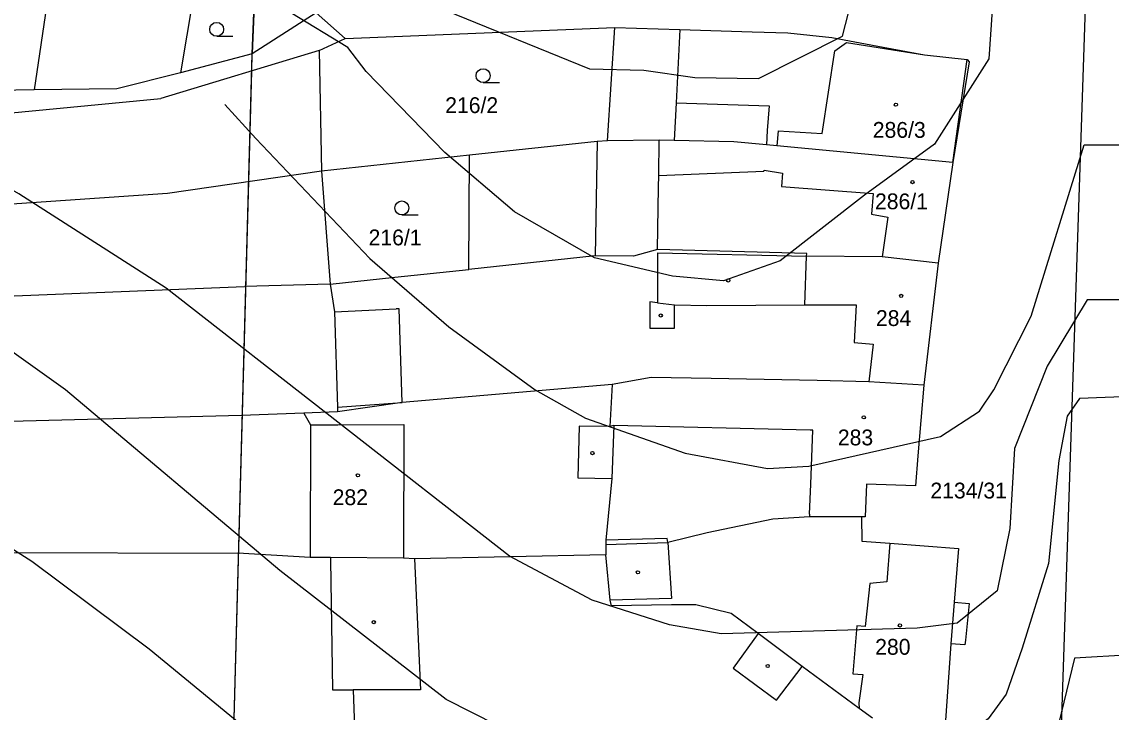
# Model space of a CAD drawing. Extents: x -555860 to -552701, y -1187050 to -1182291.
# Drawn here: x -554722.7 to -554605.7, y -1184771.9 to -1184697.7 of the extents above; entities that cross this region are included whole.
import ezdxf

# ---------------------------------------------------------------- set-up
doc = ezdxf.new("R2010")
doc.units = 0
for name, color, linetype in [('CYKLISTI_stav', 7, 'Continuous'), ('LEG_2b', 7, 'Continuous'), ('Level 25', 7, 'Continuous'), ('Level 32', 7, 'Continuous'), ('Level 40', 7, 'Continuous'), ('Level 41', 7, 'Continuous'), ('navrh_BV', 7, 'Continuous'), ('Poz předměty', 7, 'Continuous')]:
    doc.layers.add(name, color=color, linetype=linetype)

msp = doc.modelspace()

# ---------------------------------------------------------------- linework, layer by layer
at = {"layer": 'CYKLISTI_stav'}
for p, q in [((-554652.03, -1184698.53), (-554652.43, -1184706.42)), ((-554622.69, -1184712.83), (-554621.15, -1184701.75)), ((-554652.43, -1184706.42), (-554652.64, -1184710.45)), ((-554642.63, -1184709.37), (-554642.73, -1184710.92)), ((-554641.48, -1184709.43), (-554641.59, -1184711.03)), ((-554660.89, -1184710.57), (-554661.13, -1184722.87)), ((-554654.29, -1184714.23), (-554654.23, -1184710.41)), ((-554654.31, -1184715.48), (-554654.29, -1184714.23)), ((-554654.29, -1184714.23), (-554643, -1184713.77)), ((-554643, -1184713.77), (-554642.98, -1184713.66)), ((-554642.98, -1184713.66), (-554641, -1184713.97)), ((-554641, -1184713.97), (-554641.11, -1184715.42)), ((-554654.41, -1184722.17), (-554654.31, -1184715.48)), ((-554641.11, -1184715.42), (-554631.26, -1184716.14)), ((-554631.26, -1184716.14), (-554631.42, -1184718.37)), ((-554631.42, -1184718.37), (-554629.68, -1184718.69)), ((-554629.68, -1184718.69), (-554630.28, -1184722.98)), ((-554654.41, -1184722.52), (-554654.43, -1184727.9)), ((-554654.41, -1184722.52), (-554638.43, -1184722.91)), ((-554638.58, -1184728.14), (-554638.43, -1184722.91)), ((-554655.24, -1184727.8), (-554655.25, -1184730.62)), ((-554654.43, -1184727.9), (-554655.24, -1184727.8)), ((-554654.43, -1184727.9), (-554652.6, -1184728.14)), ((-554652.61, -1184730.64), (-554652.6, -1184728.14)), ((-554652.6, -1184728.14), (-554649.13, -1184728.19)), ((-554649.13, -1184728.19), (-554638.58, -1184728.14)), ((-554638.58, -1184728.14), (-554633.27, -1184728.11)), ((-554633.08, -1184728.11), (-554633.29, -1184732.17)), ((-554633.27, -1184728.11), (-554633.08, -1184728.11)), ((-554689.11, -1184728.89), (-554682.49, -1184728.57)), ((-554682.16, -1184728.55), (-554682.49, -1184728.57)), ((-554681.84, -1184738.64), (-554682.16, -1184728.55)), ((-554655.25, -1184730.62), (-554652.61, -1184730.64)), ((-554633.29, -1184732.17), (-554631.26, -1184732.37)), ((-554631.26, -1184732.37), (-554631.71, -1184736.39)), ((-554688.81, -1184739.12), (-554681.84, -1184738.64)), ((-554691.71, -1184741.03), (-554688.76, -1184741.02)), ((-554688.76, -1184741.02), (-554681.67, -1184741)), ((-554681.67, -1184741), (-554681.72, -1184755.36)), ((-554659.13, -1184741.1), (-554659.56, -1184741.22)), ((-554659.13, -1184741.1), (-554659.33, -1184746.81)), ((-554638.02, -1184741.6), (-554659.13, -1184741.1)), ((-554637.75, -1184741.61), (-554638.02, -1184741.6)), ((-554637.95, -1184747.41), (-554637.75, -1184741.61)), ((-554638.08, -1184750.62), (-554637.95, -1184747.41)), ((-554638.08, -1184750.62), (-554638.08, -1184750.92)), ((-554659.98, -1184753.88), (-554653.3, -1184753.68)), ((-554653.3, -1184753.68), (-554652.93, -1184759.71)), ((-554629.48, -1184753.75), (-554629.79, -1184757.9)), ((-554680.54, -1184755.42), (-554679.88, -1184769.53)), ((-554631.61, -1184758.09), (-554632.1, -1184762.72)), ((-554629.79, -1184757.9), (-554631.61, -1184758.09)), ((-554652.93, -1184759.71), (-554659.5, -1184759.89)), ((-554622.57, -1184760.1), (-554622.9, -1184764.57)), ((-554643.61, -1184763.47), (-554646.3, -1184767.17)), ((-554633.01, -1184762.64), (-554633.45, -1184767.78)), ((-554632.1, -1184762.72), (-554633.01, -1184762.64)), ((-554641.65, -1184770.63), (-554638.89, -1184767.02)), ((-554646.3, -1184767.17), (-554641.65, -1184770.63)), ((-554633.45, -1184767.78), (-554632.36, -1184767.87)), ((-554632.36, -1184767.87), (-554632.78, -1184770.91)), ((-554679.88, -1184769.53), (-554687.1, -1184769.51)), ((-554632.78, -1184770.91), (-554632.76, -1184771.51))]:
    msp.add_line(p, q, dxfattribs=at)
for points in [[(-554641.48, -1184709.43), (-554636.73, -1184709.69), (-554635.39, -1184700.81), (-554634.13, -1184699.94), (-554625.75, -1184701.24)], [(-554652.43, -1184706.42), (-554642.44, -1184706.74), (-554642.63, -1184709.37)]]:
    msp.add_lwpolyline(points, dxfattribs=at)
at = {"layer": 'Level 25'}
for p, q in [((-554701.78, -1184699.26), (-554700.03, -1184699.26)), ((-554673.16, -1184704.24), (-554671.41, -1184704.24)), ((-554681.89, -1184718.46), (-554680.14, -1184718.46))]:
    msp.add_line(p, q, dxfattribs=at)
for centre, radius in [((-554701.78, -1184698.51), 0.75), ((-554673.16, -1184703.49), 0.75), ((-554628.81, -1184706.61), 0.175), ((-554627.03, -1184714.93), 0.175), ((-554681.89, -1184717.71), 0.75), ((-554646.83, -1184725.5), 0.175), ((-554628.25, -1184727.17), 0.175), ((-554654.08, -1184729.27), 0.175), ((-554632.27, -1184740.22), 0.175), ((-554661.41, -1184744.06), 0.175), ((-554686.61, -1184746.45), 0.175), ((-554656.53, -1184756.88), 0.175), ((-554684.91, -1184762.24), 0.175), ((-554628.38, -1184762.59), 0.175), ((-554642.59, -1184766.95), 0.175)]:
    msp.add_circle(centre, radius, dxfattribs=at)
at = {"layer": 'Level 32'}
msp.add_lwpolyline([(-554717.6, -1184874.5), (-554713.44, -1184852.4), (-554706.92, -1184853.88), (-554706.04, -1184849.97), (-554712.7, -1184848.47), (-554700.16, -1184781.85), (-554697.96, -1184701.13), (-554696.6, -1184667.81), (-554694.47, -1184658.87), (-554690.37, -1184660.23)], dxfattribs=at)
at = {"layer": 'Level 40'}
msp.add_lwpolyline([(-554700.89, -1184706.6), (-554697.58, -1184710.26), (-554685.31, -1184723.13), (-554676.85, -1184730.48), (-554667.56, -1184737.28), (-554662.15, -1184740.32), (-554651.47, -1184744.07), (-554642.6, -1184745.73), (-554638.16, -1184745.46), (-554624.02, -1184742.27), (-554619.82, -1184739.54), (-554618.31, -1184737.26), (-554614.29, -1184729.35), (-554608.6, -1184710.94), (-554601.62, -1184710.94)], dxfattribs=at)
at = {"layer": 'Level 41'}
for points in [[(-554821.34, -1184643.77), (-554818.42, -1184648.81), (-554813.29, -1184656.72), (-554806.63, -1184663.23), (-554803.41, -1184664.98), (-554800.67, -1184666.14), (-554796.79, -1184667.11), (-554790.96, -1184667.53), (-554769.06, -1184667.11), (-554721.64, -1184669.89), (-554709.99, -1184671.97), (-554702.22, -1184675.85), (-554677.79, -1184690.8), (-554677.25, -1184696.44), (-554661.73, -1184702.75), (-554655.91, -1184702.89), (-554650.41, -1184703.69), (-554643.56, -1184703.8), (-554634.55, -1184699.23), (-554633.23, -1184694.03), (-554627.76, -1184688.75), (-554618.33, -1184676.13), (-554610.15, -1184660.6), (-554604.33, -1184651.58)], [(-554604.84, -1184668.25), (-554608.91, -1184676.41), (-554618.47, -1184696.44), (-554618.83, -1184701.69), (-554624.66, -1184710.84), (-554632.2, -1184716.34), (-554641.25, -1184723.39), (-554647.35, -1184725.53), (-554652.8, -1184725.04), (-554661.21, -1184723.06), (-554669.78, -1184718.14), (-554677.26, -1184711.76), (-554685.72, -1184703.03), (-554687.7, -1184700.46), (-554693.8, -1184696.72)], [(-554601.83, -1184727.59), (-554608.27, -1184727.59), (-554612.57, -1184734.71), (-554616.06, -1184743.57), (-554616.59, -1184752.16), (-554617.94, -1184758.87), (-554622.23, -1184762.36), (-554626.52, -1184762.9), (-554647.59, -1184763.48), (-554653.14, -1184762.51), (-554661.46, -1184759.88), (-554670.33, -1184755.16), (-554707.21, -1184726.32), (-554723.02, -1184716.2), (-554733.7, -1184710.1)], [(-554602.64, -1184737.93), (-554609.08, -1184738.2), (-554610.42, -1184740.08), (-554611.3, -1184744.85), (-554612.41, -1184755.94), (-554615.25, -1184765.05), (-554616.96, -1184769.99), (-554618.9, -1184772.63), (-554625.96, -1184778.04), (-554643.43, -1184781.09), (-554653.42, -1184780.54), (-554663.4, -1184777.49), (-554677.12, -1184770.55), (-554695.01, -1184756.69), (-554718.03, -1184737.28), (-554735.5, -1184724.8), (-554750.75, -1184716.48), (-554760.32, -1184712.77)], [(-554603.49, -1184765.74), (-554609.62, -1184766.12), (-554613.91, -1184783.84), (-554618.17, -1184790.02), (-554624.02, -1184794.82), (-554632.34, -1184796.9), (-554640.66, -1184797.73), (-554651.75, -1184797.18), (-554655.74, -1184796.74), (-554666.13, -1184794.26), (-554677.19, -1184789.48), (-554681.98, -1184786.64), (-554689.47, -1184781.23), (-554709.02, -1184765.15), (-554721.63, -1184755.72), (-554738, -1184745.32), (-554749.92, -1184738.94), (-554772.11, -1184728.96), (-554787.08, -1184723.55), (-554796.81, -1184720.58), (-554804.55, -1184718.83), (-554812.49, -1184718)]]:
    msp.add_lwpolyline(points, dxfattribs=at)
at = {"layer": 'navrh_BV'}
for p, q in [((-554694.25, -1184634.07), (-554705.66, -1184703.17)), ((-554713.39, -1184651.22), (-554721.4, -1184705.02)), ((-554696.6, -1184667.81), (-554697.96, -1184701.13)), ((-554612.53, -1184818.21), (-554608.32, -1184692.11)), ((-554691.11, -1184696.73), (-554697.96, -1184701.13)), ((-554691.11, -1184696.73), (-554687.98, -1184699.51)), ((-554687.98, -1184699.51), (-554659.02, -1184698.31)), ((-554659.78, -1184710.51), (-554659.02, -1184698.31)), ((-554659.02, -1184698.31), (-554652.03, -1184698.53)), ((-554652.03, -1184698.53), (-554644.24, -1184698.78)), ((-554644.24, -1184698.78), (-554640.42, -1184698.88)), ((-554640.42, -1184698.88), (-554635.71, -1184699.4)), ((-554690.76, -1184700.79), (-554687.98, -1184699.51)), ((-554635.71, -1184699.4), (-554630.19, -1184700.42)), ((-554690.76, -1184700.79), (-554707.77, -1184705.96)), ((-554697.96, -1184701.13), (-554705.66, -1184703.17)), ((-554690.76, -1184700.79), (-554690.53, -1184713.76)), ((-554630.19, -1184700.42), (-554625.75, -1184701.24)), ((-554625.75, -1184701.24), (-554621.15, -1184701.75)), ((-554620.96, -1184702.01), (-554622.69, -1184712.83)), ((-554621.15, -1184701.75), (-554620.96, -1184702.01)), ((-554705.66, -1184703.17), (-554712.5, -1184704.91)), ((-554721.4, -1184705.02), (-554736.82, -1184705.2)), ((-554712.5, -1184704.91), (-554721.4, -1184705.02)), ((-554759.48, -1184710.88), (-554707.77, -1184705.96)), ((-554660.89, -1184710.57), (-554674.62, -1184712.05)), ((-554659.78, -1184710.51), (-554660.89, -1184710.57)), ((-554654.23, -1184710.41), (-554659.78, -1184710.51)), ((-554652.64, -1184710.45), (-554654.23, -1184710.41)), ((-554646.24, -1184710.59), (-554652.64, -1184710.45)), ((-554642.73, -1184710.92), (-554646.24, -1184710.59)), ((-554674.62, -1184712.05), (-554690.53, -1184713.76)), ((-554674.68, -1184724.31), (-554674.62, -1184712.05)), ((-554641.59, -1184711.03), (-554642.73, -1184710.92)), ((-554622.69, -1184712.83), (-554641.59, -1184711.03)), ((-554622.69, -1184712.83), (-554624.28, -1184723.63)), ((-554690.53, -1184713.76), (-554707.05, -1184716.16)), ((-554690.53, -1184713.76), (-554689.6, -1184725.9)), ((-554707.05, -1184716.16), (-554759.01, -1184719.71)), ((-554654.41, -1184722.17), (-554657.02, -1184722.91)), ((-554638.38, -1184722.61), (-554654.41, -1184722.17)), ((-554661.13, -1184722.87), (-554674.68, -1184724.31)), ((-554657.02, -1184722.91), (-554661.13, -1184722.87)), ((-554638.43, -1184722.91), (-554638.38, -1184722.61)), ((-554630.28, -1184722.98), (-554638.43, -1184722.91)), ((-554624.28, -1184723.63), (-554630.28, -1184722.98)), ((-554624.28, -1184723.63), (-554625.81, -1184736.76)), ((-554682.64, -1184725.16), (-554674.68, -1184724.31)), ((-554689.6, -1184725.9), (-554698.8, -1184726.14)), ((-554689.6, -1184725.9), (-554682.64, -1184725.16)), ((-554689.6, -1184725.9), (-554689.11, -1184728.89)), ((-554758.36, -1184728.58), (-554698.8, -1184726.14)), ((-554689.11, -1184728.89), (-554688.81, -1184739.12)), ((-554655.11, -1184735.95), (-554659.29, -1184736.68)), ((-554648.65, -1184736.06), (-554655.11, -1184735.95)), ((-554637.28, -1184736.26), (-554648.65, -1184736.06)), ((-554631.71, -1184736.39), (-554637.28, -1184736.26)), ((-554625.81, -1184736.76), (-554631.71, -1184736.39)), ((-554659.29, -1184736.68), (-554681.84, -1184738.64)), ((-554659.29, -1184736.68), (-554659.56, -1184741.22)), ((-554625.81, -1184736.76), (-554626.45, -1184744.36)), ((-554681.84, -1184738.64), (-554688.8, -1184739.62)), ((-554699.1, -1184740.03), (-554776.18, -1184741.97)), ((-554692.41, -1184739.76), (-554699.1, -1184740.03)), ((-554688.8, -1184739.62), (-554692.41, -1184739.76)), ((-554692.41, -1184739.76), (-554691.71, -1184741.03)), ((-554688.81, -1184739.12), (-554688.8, -1184739.62)), ((-554691.71, -1184741.03), (-554691.75, -1184755.29)), ((-554662.84, -1184741.17), (-554663, -1184746.71)), ((-554659.56, -1184741.22), (-554662.84, -1184741.17)), ((-554626.45, -1184744.36), (-554626.72, -1184747.58)), ((-554663, -1184746.71), (-554659.33, -1184746.81)), ((-554659.33, -1184746.81), (-554659.97, -1184753.43)), ((-554631.99, -1184747.41), (-554632.1, -1184750.9)), ((-554626.72, -1184747.58), (-554631.99, -1184747.41)), ((-554642.02, -1184751.16), (-554649.1, -1184752.64)), ((-554638.08, -1184750.92), (-554642.02, -1184751.16)), ((-554632.5, -1184750.9), (-554638.08, -1184750.92)), ((-554632.1, -1184750.9), (-554632.5, -1184750.9)), ((-554632.5, -1184750.9), (-554632.47, -1184753.53)), ((-554649.1, -1184752.64), (-554653.3, -1184753.68)), ((-554659.98, -1184753.88), (-554659.99, -1184755)), ((-554659.97, -1184753.43), (-554659.98, -1184753.88)), ((-554653.37, -1184753.24), (-554659.97, -1184753.43)), ((-554653.3, -1184753.68), (-554653.37, -1184753.24)), ((-554632.47, -1184753.53), (-554629.48, -1184753.75)), ((-554629.48, -1184753.75), (-554622.1, -1184754.31)), ((-554775.16, -1184754.66), (-554699.5, -1184754.82)), ((-554691.75, -1184755.29), (-554699.5, -1184754.82)), ((-554689.55, -1184755.3), (-554691.75, -1184755.29)), ((-554681.72, -1184755.36), (-554689.55, -1184755.3)), ((-554689.55, -1184755.3), (-554689.55, -1184755.57)), ((-554680.54, -1184755.42), (-554681.72, -1184755.36)), ((-554659.99, -1184755), (-554680.54, -1184755.42)), ((-554659.5, -1184759.89), (-554659.99, -1184755)), ((-554622.1, -1184754.31), (-554622.57, -1184760.1)), ((-554689.55, -1184755.57), (-554689.35, -1184769.51)), ((-554659.38, -1184760.48), (-554659.5, -1184759.89)), ((-554652.91, -1184760.36), (-554659.38, -1184760.48)), ((-554650.31, -1184760.36), (-554652.91, -1184760.36)), ((-554646.5, -1184761.29), (-554650.31, -1184760.36)), ((-554622.57, -1184760.1), (-554620.96, -1184760.22)), ((-554620.96, -1184760.22), (-554621.35, -1184764.16)), ((-554643.61, -1184763.47), (-554646.5, -1184761.29)), ((-554638.89, -1184767.02), (-554643.61, -1184763.47)), ((-554622.9, -1184764.57), (-554623.61, -1184774.35)), ((-554621.4, -1184764.68), (-554622.9, -1184764.57)), ((-554621.35, -1184764.16), (-554621.4, -1184764.68)), ((-554632.76, -1184771.51), (-554638.89, -1184767.02)), ((-554689.35, -1184769.51), (-554687.1, -1184769.51)), ((-554687.1, -1184769.51), (-554686.69, -1184782.27)), ((-554631.32, -1184772.57), (-554632.76, -1184771.51))]:
    msp.add_line(p, q, dxfattribs=at)
at = {"layer": 'Poz předměty'}
for points in [[(-554698.01, -1184702.99), (-554697.96, -1184701.13)], [(-554712.7, -1184848.47), (-554700.16, -1184781.85), (-554698.01, -1184702.99)]]:
    msp.add_lwpolyline(points, dxfattribs=at)

# ---------------------------------------------------------------- texts
at = {"layer": 'LEG_2b'}
for s, p in [('216/2', (-554677.23, -1184707.51)), ('286/3', (-554631.3, -1184710.17)), ('286/1', (-554631.06, -1184717.85)), ('216/1', (-554685.46, -1184721.73)), ('284', (-554630.96, -1184730.4)), ('283', (-554635.05, -1184743.23)), ('2134/31', (-554625.11, -1184748.94)), ('282', (-554689.32, -1184749.66)), ('280', (-554631.04, -1184765.74))]:
    msp.add_text(s, height=1.7, dxfattribs=at).set_placement(p)

doc.saveas('drawing.dxf')
